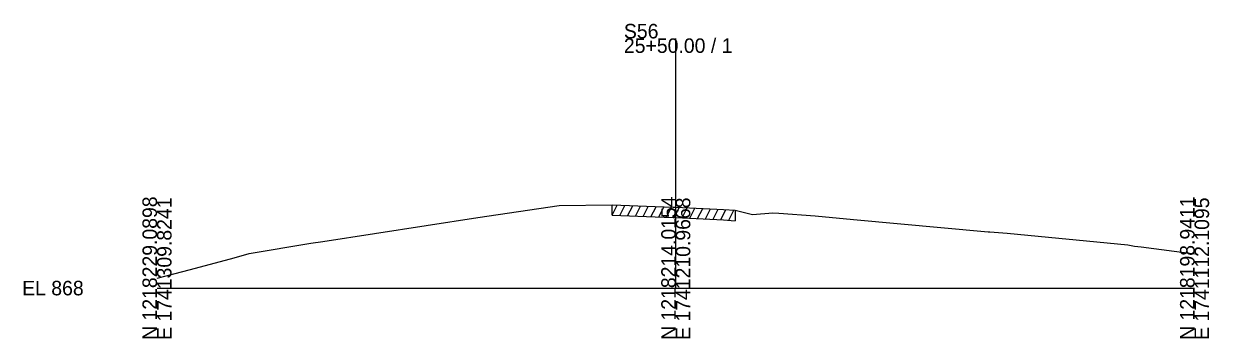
# Model space of a CAD drawing. Extents: x -26 to 1203, y -10 to 19541.
# Drawn here: x -25.7 to 202.8, y 490.3 to 551 of the extents above; entities that cross this region are included whole.
import ezdxf

# ---------------------------------------------------------------- set-up
doc = ezdxf.new("R2010")
doc.units = 0
for name, color, linetype in [('RD_GPK_XS_Cell', 7, 'Continuous'), ('RD_XS_ExGround', 7, 'Continuous'), ('RD_XS_ExPaveRet', 7, 'Continuous'), ('RD_XS_TX_Elev_EX', 7, 'Continuous')]:
    doc.layers.add(name, color=color, linetype=linetype)

msp = doc.modelspace()

# ---------------------------------------------------------------- linework, layer by layer
at = {"layer": 'RD_GPK_XS_Cell'}
for p, q in [((100, 500), (100, 548.19)), ((0, 500), (100, 500)), ((100, 500), (200, 500))]:
    msp.add_line(p, q, dxfattribs=at)
at = {"layer": 'RD_XS_ExGround'}
msp.add_lwpolyline([(0, 501.89), (6.43, 503.62), (14.86, 505.84), (17.79, 506.68), (29.68, 508.64), (31.98, 509.02), (61.87, 513.62), (77.51, 515.91), (87.71, 516.06), (96.03, 515.72), (99.48, 515.64), (100, 515.62), (109.23, 515.18), (111.44, 515.01), (114.79, 514.2), (118.7, 514.55), (119.86, 514.48), (126.88, 513.92), (134.27, 513.24), (160.21, 510.87), (160.53, 510.85), (163.9, 510.57), (187.15, 508.33), (188.4, 508.07), (189.69, 507.95), (200, 506.58)], dxfattribs=at)
at = {"layer": 'RD_XS_ExPaveRet'}
for p, q in [((87.71, 514.06), (87.71, 516.06)), ((87.71, 514.06), (88.69, 516.02)), ((89.21, 514), (90.19, 515.96)), ((90.71, 513.94), (91.69, 515.9)), ((92.21, 513.87), (93.19, 515.83)), ((93.71, 513.81), (94.69, 515.77)), ((95.21, 513.75), (96.19, 515.71)), ((96.71, 513.7), (97.7, 515.68)), ((98.21, 513.67), (99.2, 515.65)), ((99.71, 513.63), (100.69, 515.59)), ((101.21, 513.56), (102.19, 515.51)), ((102.71, 513.49), (103.69, 515.44)), ((104.21, 513.42), (105.19, 515.37)), ((105.71, 513.35), (106.69, 515.3)), ((107.21, 513.28), (108.19, 515.23)), ((108.71, 513.2), (109.68, 515.14)), ((110.21, 513.1), (111.18, 515.03)), ((111.44, 515.01), (111.44, 513.01)), ((87.71, 514.06), (96.03, 513.72)), ((96.03, 513.72), (99.48, 513.64)), ((99.48, 513.64), (100, 513.62)), ((100, 513.62), (109.23, 513.18)), ((109.23, 513.18), (111.44, 513.01))]:
    msp.add_line(p, q, dxfattribs=at)

# ---------------------------------------------------------------- texts
at = {"layer": 'RD_GPK_XS_Cell'}
for s, p in [('S56', (90, 548.19)), ('25+50.00 / 1', (90, 545.39)), ('EL 868', (-26, 498.6))]:
    msp.add_text(s, height=2.8, dxfattribs=at).set_placement(p)
for s, p in [('N 1218229.0898', (0, 490)), ('E 1741309.8241', (2.8, 490)), ('N 1218214.0154', (100, 490)), ('E 1741210.9668', (102.8, 490)), ('N 1218198.9411', (200, 490)), ('E 1741112.1095', (202.8, 490))]:
    msp.add_text(s, height=2.8, rotation=90, dxfattribs=at).set_placement(p)
at = {"layer": 'RD_XS_TX_Elev_EX'}
msp.add_text('875.81', height=0.1, rotation=90, dxfattribs=at).set_placement((100.1, 515.62))

doc.saveas('drawing.dxf')
